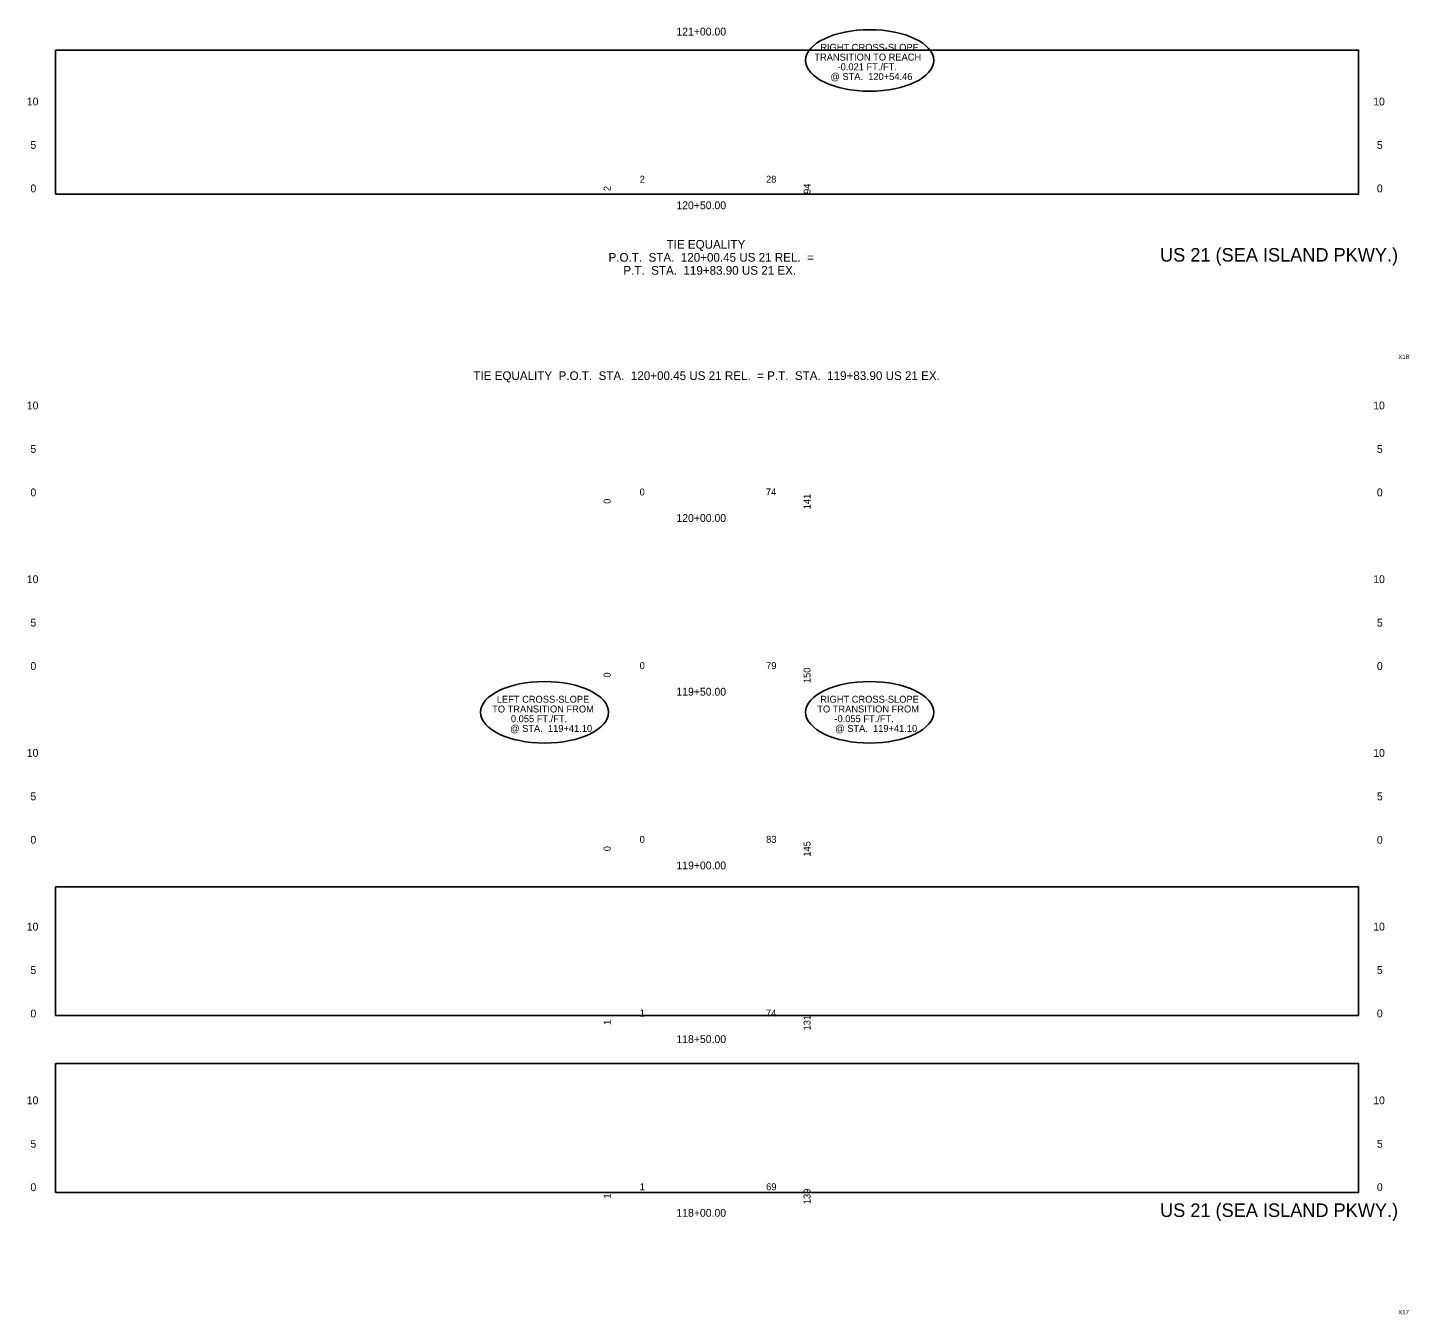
# Model space of a CAD drawing. Extents: x 971 to 1131, y 2203 to 6043.
# Drawn here: x 971.5 to 1130.5, y 5602.7 to 5750.8 of the extents above; entities that cross this region are included whole.
import ezdxf

# ---------------------------------------------------------------- set-up
doc = ezdxf.new("R2010")
doc.units = 0
for name, color, linetype in [('RD_SHT_Misc1', 7, 'Continuous'), ('RD_SHT_ShtClip', 7, 'Continuous'), ('RD_SHT_TX', 7, 'Continuous'), ('RD_TX_StaOff', 7, 'Continuous'), ('RD_XS_TX_Station', 7, 'Continuous')]:
    doc.layers.add(name, color=color, linetype=linetype)

msp = doc.modelspace()

# ---------------------------------------------------------------- linework, layer by layer
at = {"layer": 'RD_SHT_ShtClip'}
for points in [[(974.73, 5748.24), (1124.73, 5748.24), (1124.73, 5731.66), (974.73, 5731.66)], [(974.73, 5651.91), (1124.73, 5651.91), (1124.73, 5637.09), (974.73, 5637.09)], [(974.73, 5631.55), (1124.73, 5631.55), (1124.73, 5616.72), (974.73, 5616.72)]]:
    msp.add_lwpolyline(points, close=True, dxfattribs=at)
at = {"layer": 'RD_TX_StaOff'}
for centre in [(1068.45, 5747.05), (1031.02, 5672), (1068.45, 5672)]:
    msp.add_ellipse(centre, major_axis=(7.37, 0), ratio=0.480649, dxfattribs=at)

# ---------------------------------------------------------------- texts
at = {"layer": 'RD_SHT_Misc1'}
for s, p in [('2', (1041.98, 5732.97)), ('28', (1056.52, 5732.97)), ('0', (1041.97, 5696.97)), ('74', (1056.51, 5696.97)), ('0', (1041.97, 5676.97)), ('79', (1056.53, 5676.97)), ('0', (1041.97, 5656.97)), ('83', (1056.53, 5656.97)), ('1', (1041.98, 5636.97)), ('74', (1056.51, 5636.97)), ('1', (1041.98, 5616.97)), ('69', (1056.53, 5616.97))]:
    msp.add_text(s, height=0.8, dxfattribs=at).set_placement(p)
for s, p in [('2', (1038.63, 5732.01)), ('94', (1061.64, 5731.68)), ('141', (1061.64, 5695.37)), ('0', (1038.63, 5696)), ('0', (1038.63, 5676)), ('150', (1061.64, 5675.36)), ('0', (1038.63, 5656)), ('145', (1061.64, 5655.38)), ('1', (1038.63, 5636.01)), ('131', (1061.64, 5635.37)), ('1', (1038.63, 5616.01)), ('139', (1061.64, 5615.37))]:
    msp.add_text(s, height=0.8, rotation=90, dxfattribs=at).set_placement(p)
at = {"layer": 'RD_SHT_TX'}
for s, height, p in [('10', 0.9, (971.42, 5741.87)), ('10', 0.9, (1126.42, 5741.87)), ('5', 0.9, (971.84, 5736.87)), ('5', 0.9, (1126.84, 5736.87)), ('0', 0.9, (971.84, 5731.87)), ('0', 0.9, (1126.84, 5731.87)), ('US 21 (SEA ISLAND PKWY.)', 1.5625, (1101.88, 5723.89)), ('10', 0.9, (971.42, 5706.87)), ('10', 0.9, (1126.42, 5706.87)), ('5', 0.9, (971.84, 5701.87)), ('5', 0.9, (1126.84, 5701.87)), ('0', 0.9, (971.84, 5696.87)), ('0', 0.9, (1126.84, 5696.87)), ('10', 0.9, (971.42, 5686.87)), ('10', 0.9, (1126.42, 5686.87)), ('5', 0.9, (971.84, 5681.87)), ('5', 0.9, (1126.84, 5681.87)), ('0', 0.9, (971.84, 5676.87)), ('0', 0.9, (1126.84, 5676.87)), ('10', 0.9, (971.42, 5666.87)), ('10', 0.9, (1126.42, 5666.87)), ('5', 0.9, (971.84, 5661.87)), ('5', 0.9, (1126.84, 5661.87)), ('0', 0.9, (971.84, 5656.87)), ('0', 0.9, (1126.84, 5656.87)), ('10', 0.9, (971.42, 5646.87)), ('10', 0.9, (1126.42, 5646.87)), ('5', 0.9, (971.84, 5641.87)), ('5', 0.9, (1126.84, 5641.87)), ('0', 0.9, (971.84, 5636.87)), ('0', 0.9, (1126.84, 5636.87)), ('10', 0.9, (971.42, 5626.87)), ('10', 0.9, (1126.42, 5626.87)), ('5', 0.9, (971.84, 5621.87)), ('5', 0.9, (1126.84, 5621.87)), ('0', 0.9, (971.84, 5616.87)), ('0', 0.9, (1126.84, 5616.87)), ('US 21 (SEA ISLAND PKWY.)', 1.5625, (1101.88, 5613.89))]:
    msp.add_text(s, height=height, dxfattribs=at).set_placement(p)
for s, p in [('X18', (1129.31, 5712.68)), ('X17', (1129.3, 5602.68))]:
    msp.add_text(s, height=0.5, rotation=360, dxfattribs=at).set_placement(p)
at = {"layer": 'RD_TX_StaOff'}
for s, p in [('TRANSITION TO REACH', (1062.08, 5747.04)), ('RIGHT CROSS-SLOPE', (1062.76, 5748.16)), ('-0.021 FT./FT.', (1064.75, 5745.92)), ('@ STA.  120+54.46', (1063.93, 5744.8)), ('RIGHT CROSS-SLOPE', (1062.76, 5673.1)), ('TO TRANSITION FROM', (1062.42, 5671.98)), ('-0.055 FT./FT.', (1064.39, 5670.86)), ('@ STA.  119+41.10', (1064.48, 5669.74))]:
    msp.add_text(s, height=0.8, rotation=360, dxfattribs=at).set_placement(p)
for s, height, p in [('TIE EQUALITY', 1, (1045.07, 5725.38)), ('P.O.T.  STA.  120+00.45 US 21 REL.  =', 1, (1038.39, 5723.88)), ('P.T.  STA.  119+83.90 US 21 EX.', 1, (1040.1, 5722.38)), ('TIE EQUALITY  P.O.T.  STA.  120+00.45 US 21 REL.  = P.T.  STA.  119+83.90 US 21 EX.', 1, (1022.83, 5710.26)), ('LEFT CROSS-SLOPE', 0.8, (1025.53, 5673.1)), ('TO TRANSITION FROM', 0.8, (1024.99, 5671.98)), ('0.055 FT./FT.', 0.8, (1027.15, 5670.86)), ('@ STA.  119+41.10', 0.8, (1027.06, 5669.74))]:
    msp.add_text(s, height=height, dxfattribs=at).set_placement(p)
at = {"layer": 'RD_XS_TX_Station'}
for s, p in [('121+00.00', (1046.2, 5749.92)), ('120+50.00', (1046.2, 5729.92)), ('120+00.00', (1046.2, 5693.92)), ('119+50.00', (1046.2, 5673.92)), ('119+00.00', (1046.2, 5653.92)), ('118+50.00', (1046.2, 5633.92)), ('118+00.00', (1046.2, 5613.92))]:
    msp.add_text(s, height=0.9, dxfattribs=at).set_placement(p)

doc.saveas('drawing.dxf')
